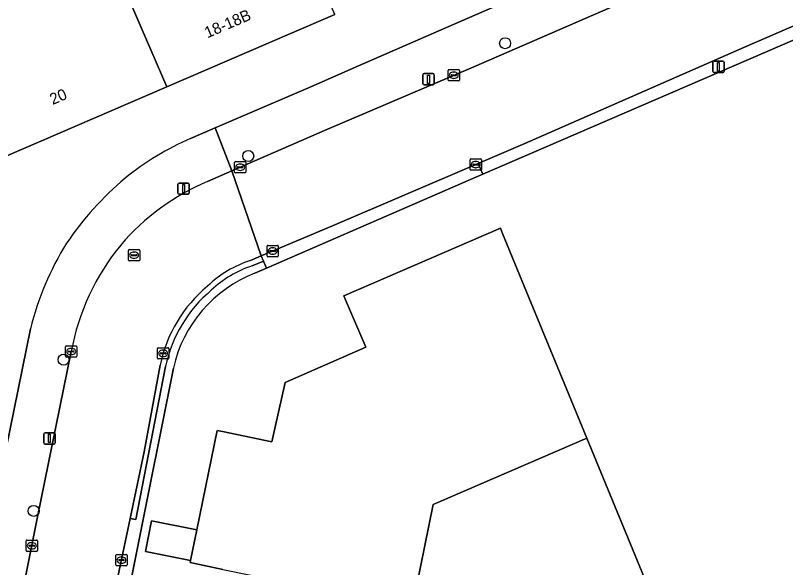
# Model space of a CAD drawing. Extents: x 158086 to 159499, y 382904 to 383981.
# Drawn here: x 158796.6 to 158864.8, y 383041 to 383089.9 of the extents above; entities that cross this region are included whole.
import ezdxf

# ---------------------------------------------------------------- set-up
doc = ezdxf.new("R2010")
doc.units = 0
for name, color, linetype in [('IMGEO_Boom', 7, 'Continuous'), ('IMGEO_Erf', 7, 'Continuous'), ('IMGEO_Kolk', 7, 'Continuous'), ('IMGEO_Lichtmast', 7, 'Continuous'), ('IMGEO_Pand', 7, 'Continuous'), ('IMGEO_Pand_nummerreeks', 7, 'Continuous'), ('IMGEO_Parkeervlak_open', 7, 'Continuous'), ('IMGEO_Rijbaan_lokaal_open', 7, 'Continuous'), ('IMGEO_Rioolput', 7, 'Continuous'), ('IMGEO_Voetpad_open', 7, 'Continuous')]:
    doc.layers.add(name, color=color, linetype=linetype)

msp = doc.modelspace()

# ---------------------------------------------------------------- linework, layer by layer
at = {"layer": 'IMGEO_Boom'}
for centre in [(158839.951, 383087.397), (158817.188, 383077.403), (158800.831, 383059.368), (158798.187, 383045.98)]:
    msp.add_circle(centre, 0.489, dxfattribs=at)
at = {"layer": 'IMGEO_Erf'}
for points in [[(158975.23, 383135.031), (158942.876, 383121.069), (158936.852, 383118.469), (158837.977, 383075.801), (158837.572, 383075.626), (158818.806, 383067.474), (158817.768, 383067.023)], [(158814.931, 383040.798), (158812.043, 383041.411), (158812.078, 383041.581), (158808.08, 383042.398), (158808.633, 383045.106), (158812.631, 383044.289), (158814.431, 383053.094), (158814.905, 383052.997), (158819.271, 383052.105), (158820.475, 383057.358), (158827.618, 383060.492), (158825.82, 383064.663), (158825.666, 383065.019), (158839.541, 383071.003), (158839.731, 383070.541), (158841.445, 383066.38), (158847.197, 383052.411), (158853.12, 383038.028)], [(158810.559, 383058.63), (158807.3, 383042.268), (158806.424, 383037.984), (158805.395, 383032.947), (158801.03, 383011.785), (158799.863, 383006.073)]]:
    msp.add_lwpolyline(points, dxfattribs=at)
msp.add_arc((158822.065, 383056.04), 11.794, 111.36692, 167.31253, dxfattribs=at)
at = {"layer": 'IMGEO_Kolk'}
for p, q in [((158834.899, 383084.135), (158834.899, 383084.987)), ((158834.974, 383085.061), (158835.826, 383085.061)), ((158835.9, 383084.987), (158835.9, 383084.135)), ((158835.158, 383084.555), (158835.158, 383084.567)), ((158835.596, 383084.518), (158835.198, 383084.518)), ((158835.201, 383084.604), (158835.599, 383084.604)), ((158835.41, 383084.281), (158835.385, 383084.281)), ((158835.387, 383084.841), (158835.412, 383084.841)), ((158835.642, 383084.567), (158835.642, 383084.555)), ((158835.826, 383084.061), (158834.974, 383084.061)), ((158815.98, 383075.991), (158815.98, 383076.843)), ((158816.055, 383076.917), (158816.907, 383076.917)), ((158816.981, 383076.843), (158816.981, 383075.991)), ((158836.844, 383076.224), (158836.844, 383077.076)), ((158836.919, 383077.15), (158837.771, 383077.15)), ((158837.332, 383076.93), (158837.357, 383076.93)), ((158837.845, 383077.076), (158837.845, 383076.224)), ((158816.239, 383076.411), (158816.239, 383076.423)), ((158816.677, 383076.374), (158816.279, 383076.374)), ((158816.282, 383076.46), (158816.68, 383076.46)), ((158816.491, 383076.137), (158816.466, 383076.137)), ((158816.468, 383076.697), (158816.493, 383076.697)), ((158816.723, 383076.423), (158816.723, 383076.411)), ((158837.771, 383076.15), (158836.919, 383076.15)), ((158837.103, 383076.644), (158837.103, 383076.656)), ((158837.541, 383076.607), (158837.143, 383076.607)), ((158837.146, 383076.693), (158837.544, 383076.693)), ((158837.355, 383076.37), (158837.33, 383076.37)), ((158837.587, 383076.656), (158837.587, 383076.644)), ((158816.907, 383075.917), (158816.055, 383075.917)), ((158818.856, 383068.566), (158818.856, 383069.418)), ((158818.931, 383069.492), (158819.783, 383069.492)), ((158819.344, 383069.272), (158819.369, 383069.272)), ((158819.857, 383069.418), (158819.857, 383068.566)), ((158819.115, 383068.986), (158819.115, 383068.998)), ((158819.553, 383068.949), (158819.155, 383068.949)), ((158819.158, 383069.035), (158819.556, 383069.035)), ((158819.367, 383068.712), (158819.342, 383068.712)), ((158819.599, 383068.998), (158819.599, 383068.986)), ((158819.783, 383068.492), (158818.931, 383068.492)), ((158801.009, 383059.67), (158801.009, 383060.522)), ((158801.084, 383060.596), (158801.936, 383060.596)), ((158801.497, 383060.376), (158801.522, 383060.376)), ((158802.01, 383060.522), (158802.01, 383059.67)), ((158809.226, 383060.433), (158810.078, 383060.433)), ((158801.268, 383060.09), (158801.268, 383060.102)), ((158801.706, 383060.053), (158801.308, 383060.053)), ((158801.311, 383060.139), (158801.709, 383060.139)), ((158801.52, 383059.816), (158801.495, 383059.816)), ((158801.752, 383060.102), (158801.752, 383060.09)), ((158809.151, 383059.507), (158809.151, 383060.359)), ((158809.41, 383059.927), (158809.41, 383059.939)), ((158809.848, 383059.89), (158809.45, 383059.89)), ((158809.453, 383059.976), (158809.851, 383059.976)), ((158809.639, 383060.213), (158809.664, 383060.213)), ((158809.894, 383059.939), (158809.894, 383059.927)), ((158810.152, 383060.359), (158810.152, 383059.507)), ((158801.936, 383059.596), (158801.084, 383059.596)), ((158810.078, 383059.433), (158809.226, 383059.433)), ((158809.662, 383059.653), (158809.637, 383059.653)), ((158797.52, 383042.47), (158797.52, 383043.322)), ((158797.595, 383043.396), (158798.447, 383043.396)), ((158798.521, 383043.322), (158798.521, 383042.47)), ((158797.779, 383042.89), (158797.779, 383042.902)), ((158798.217, 383042.853), (158797.819, 383042.853)), ((158797.822, 383042.939), (158798.22, 383042.939)), ((158798.008, 383043.176), (158798.033, 383043.176)), ((158798.263, 383042.902), (158798.263, 383042.89)), ((158798.447, 383042.396), (158797.595, 383042.396)), ((158798.031, 383042.616), (158798.006, 383042.616)), ((158805.455, 383041.196), (158805.455, 383042.048)), ((158805.53, 383042.122), (158806.382, 383042.122)), ((158806.456, 383042.048), (158806.456, 383041.196)), ((158805.714, 383041.616), (158805.714, 383041.628)), ((158806.152, 383041.579), (158805.754, 383041.579)), ((158805.757, 383041.665), (158806.155, 383041.665)), ((158805.966, 383041.342), (158805.941, 383041.342)), ((158805.943, 383041.902), (158805.968, 383041.902)), ((158806.198, 383041.628), (158806.198, 383041.616)), ((158806.382, 383041.122), (158805.53, 383041.122))]:
    msp.add_line(p, q, dxfattribs=at)
for points in [[(158834.899, 383084.135), (158834.899, 383084.987)], [(158834.974, 383085.061), (158835.826, 383085.061)], [(158835.9, 383084.987), (158835.9, 383084.135)], [(158835.826, 383084.061), (158834.974, 383084.061)], [(158815.98, 383075.991), (158815.98, 383076.843)], [(158816.055, 383076.917), (158816.907, 383076.917)], [(158816.981, 383076.843), (158816.981, 383075.991)], [(158836.844, 383076.224), (158836.844, 383077.076)], [(158836.919, 383077.15), (158837.771, 383077.15)], [(158837.845, 383077.076), (158837.845, 383076.224)], [(158837.771, 383076.15), (158836.919, 383076.15)], [(158816.907, 383075.917), (158816.055, 383075.917)], [(158818.856, 383068.566), (158818.856, 383069.418)], [(158818.931, 383069.492), (158819.783, 383069.492)], [(158819.857, 383069.418), (158819.857, 383068.566)], [(158819.783, 383068.492), (158818.931, 383068.492)], [(158801.009, 383059.67), (158801.009, 383060.522)], [(158801.084, 383060.596), (158801.936, 383060.596)], [(158802.01, 383060.522), (158802.01, 383059.67)], [(158809.226, 383060.433), (158810.078, 383060.433)], [(158809.151, 383059.507), (158809.151, 383060.359)], [(158810.152, 383060.359), (158810.152, 383059.507)], [(158801.936, 383059.596), (158801.084, 383059.596)], [(158810.078, 383059.433), (158809.226, 383059.433)], [(158797.52, 383042.47), (158797.52, 383043.322)], [(158797.595, 383043.396), (158798.447, 383043.396)], [(158798.521, 383043.322), (158798.521, 383042.47)], [(158798.447, 383042.396), (158797.595, 383042.396)], [(158805.455, 383041.196), (158805.455, 383042.048)], [(158805.53, 383042.122), (158806.382, 383042.122)], [(158806.456, 383042.048), (158806.456, 383041.196)], [(158806.382, 383041.122), (158805.53, 383041.122)]]:
    msp.add_lwpolyline(points, dxfattribs=at)
for centre, radius, start, end in [((158834.976, 383084.985), 0.0765, 91.55205, 178.44795), ((158834.976, 383084.985), 0.0765, 91.55205, 178.44795), ((158835.824, 383084.985), 0.0765, 1.55205, 88.44795), ((158835.824, 383084.985), 0.0765, 1.55205, 88.44795), ((158835.198, 383084.564), 0.0403, 85.87752, 175.75265), ((158835.195, 383084.554), 0.0366, 178.93798, 274.71019), ((158835.599, 383084.561), 0.043, 264.86636, 352.45326), ((158835.603, 383084.566), 0.0386, 1.73085, 96.63898), ((158834.976, 383084.137), 0.0765, 181.55205, 268.44795), ((158834.976, 383084.137), 0.0765, 181.55205, 268.44795), ((158835.824, 383084.137), 0.0765, 271.55205, 358.44795), ((158835.824, 383084.137), 0.0765, 271.55205, 358.44795), ((158816.057, 383076.841), 0.0765, 91.55205, 178.44795), ((158816.057, 383076.841), 0.0765, 91.55205, 178.44795), ((158816.905, 383076.841), 0.0765, 1.55205, 88.44795), ((158816.905, 383076.841), 0.0765, 1.55205, 88.44795), ((158836.921, 383077.074), 0.0765, 91.55205, 178.44795), ((158836.921, 383077.074), 0.0765, 91.55205, 178.44795), ((158837.769, 383077.074), 0.0765, 1.55205, 88.44795), ((158837.769, 383077.074), 0.0765, 1.55205, 88.44795), ((158816.279, 383076.42), 0.0403, 85.87752, 175.75265), ((158816.276, 383076.41), 0.0366, 178.93798, 274.71019), ((158816.68, 383076.417), 0.043, 264.86636, 352.45326), ((158816.684, 383076.422), 0.0386, 1.73085, 96.63898), ((158836.921, 383076.226), 0.0765, 181.55205, 268.44795), ((158836.921, 383076.226), 0.0765, 181.55205, 268.44795), ((158837.143, 383076.653), 0.0403, 85.87752, 175.75265), ((158837.14, 383076.643), 0.0366, 178.93798, 274.71019), ((158837.544, 383076.65), 0.043, 264.86636, 352.45326), ((158837.548, 383076.655), 0.0386, 1.73085, 96.63898), ((158837.769, 383076.226), 0.0765, 271.55205, 358.44795), ((158837.769, 383076.226), 0.0765, 271.55205, 358.44795), ((158816.057, 383075.993), 0.0765, 181.55205, 268.44795), ((158816.057, 383075.993), 0.0765, 181.55205, 268.44795), ((158816.905, 383075.993), 0.0765, 271.55205, 358.44795), ((158816.905, 383075.993), 0.0765, 271.55205, 358.44795), ((158818.933, 383069.416), 0.0765, 91.55205, 178.44795), ((158818.933, 383069.416), 0.0765, 91.55205, 178.44795), ((158819.781, 383069.416), 0.0765, 1.55205, 88.44795), ((158819.781, 383069.416), 0.0765, 1.55205, 88.44795), ((158818.933, 383068.568), 0.0765, 181.55205, 268.44795), ((158818.933, 383068.568), 0.0765, 181.55205, 268.44795), ((158819.155, 383068.995), 0.0403, 85.87752, 175.75265), ((158819.152, 383068.985), 0.0366, 178.93798, 274.71019), ((158819.556, 383068.992), 0.043, 264.86636, 352.45326), ((158819.56, 383068.997), 0.0386, 1.73085, 96.63898), ((158819.781, 383068.568), 0.0765, 271.55205, 358.44795), ((158819.781, 383068.568), 0.0765, 271.55205, 358.44795), ((158801.086, 383060.52), 0.0765, 91.55205, 178.44795), ((158801.086, 383060.52), 0.0765, 91.55205, 178.44795), ((158801.934, 383060.52), 0.0765, 1.55205, 88.44795), ((158801.934, 383060.52), 0.0765, 1.55205, 88.44795), ((158809.228, 383060.357), 0.0765, 91.55205, 178.44795), ((158809.228, 383060.357), 0.0765, 91.55205, 178.44795), ((158810.076, 383060.357), 0.0765, 1.55205, 88.44795), ((158810.076, 383060.357), 0.0765, 1.55205, 88.44795), ((158801.308, 383060.099), 0.0403, 85.87752, 175.75265), ((158801.305, 383060.089), 0.0366, 178.93798, 274.71019), ((158801.709, 383060.096), 0.043, 264.86636, 352.45326), ((158801.713, 383060.101), 0.0386, 1.73085, 96.63898), ((158809.45, 383059.936), 0.0403, 85.87752, 175.75265), ((158809.447, 383059.926), 0.0366, 178.93798, 274.71019), ((158809.851, 383059.933), 0.043, 264.86636, 352.45326), ((158809.855, 383059.938), 0.0386, 1.73085, 96.63898), ((158801.086, 383059.672), 0.0765, 181.55205, 268.44795), ((158801.086, 383059.672), 0.0765, 181.55205, 268.44795), ((158801.934, 383059.672), 0.0765, 271.55205, 358.44795), ((158801.934, 383059.672), 0.0765, 271.55205, 358.44795), ((158809.228, 383059.509), 0.0765, 181.55205, 268.44795), ((158809.228, 383059.509), 0.0765, 181.55205, 268.44795), ((158810.076, 383059.509), 0.0765, 271.55205, 358.44795), ((158810.076, 383059.509), 0.0765, 271.55205, 358.44795), ((158797.597, 383043.32), 0.0765, 91.55205, 178.44795), ((158797.597, 383043.32), 0.0765, 91.55205, 178.44795), ((158798.445, 383043.32), 0.0765, 1.55205, 88.44795), ((158798.445, 383043.32), 0.0765, 1.55205, 88.44795), ((158797.819, 383042.899), 0.0403, 85.87752, 175.75265), ((158797.816, 383042.889), 0.0366, 178.93798, 274.71019), ((158798.22, 383042.896), 0.043, 264.86636, 352.45326), ((158798.224, 383042.901), 0.0386, 1.73085, 96.63898), ((158797.597, 383042.472), 0.0765, 181.55205, 268.44795), ((158797.597, 383042.472), 0.0765, 181.55205, 268.44795), ((158798.445, 383042.472), 0.0765, 271.55205, 358.44795), ((158798.445, 383042.472), 0.0765, 271.55205, 358.44795), ((158805.532, 383042.046), 0.0765, 91.55205, 178.44795), ((158805.532, 383042.046), 0.0765, 91.55205, 178.44795), ((158806.38, 383042.046), 0.0765, 1.55205, 88.44795), ((158806.38, 383042.046), 0.0765, 1.55205, 88.44795), ((158805.754, 383041.625), 0.0403, 85.87752, 175.75265), ((158805.751, 383041.615), 0.0366, 178.93798, 274.71019), ((158806.155, 383041.622), 0.043, 264.86636, 352.45326), ((158806.159, 383041.627), 0.0386, 1.73085, 96.63898), ((158805.532, 383041.198), 0.0765, 181.55205, 268.44795), ((158805.532, 383041.198), 0.0765, 181.55205, 268.44795), ((158806.38, 383041.198), 0.0765, 271.55205, 358.44795), ((158806.38, 383041.198), 0.0765, 271.55205, 358.44795)]:
    msp.add_arc(centre, radius, start, end, dxfattribs=at)
for centre, major_axis, ratio, start_param, end_param in [((158835.386, 383084.561), (-0.387, 0.002), 0.722429, 4.712389, 7.853982), ((158835.411, 383084.561), (-0.39, 0.002), 0.717154, 1.570796, 4.712389), ((158837.331, 383076.65), (-0.387, 0.002), 0.722429, 4.712389, 7.853982), ((158837.356, 383076.65), (-0.39, 0.002), 0.717154, 1.570796, 4.712389), ((158816.467, 383076.417), (-0.387, 0.002), 0.722429, 4.712389, 7.853982), ((158816.492, 383076.417), (-0.39, 0.002), 0.717154, 1.570796, 4.712389), ((158819.343, 383068.992), (-0.387, 0.002), 0.722429, 4.712389, 7.853982), ((158819.368, 383068.992), (-0.39, 0.002), 0.717154, 1.570796, 4.712389), ((158801.496, 383060.096), (-0.387, 0.002), 0.722429, 4.712389, 7.853982), ((158801.521, 383060.096), (-0.39, 0.002), 0.717154, 1.570796, 4.712389), ((158809.638, 383059.933), (-0.387, 0.002), 0.722429, 4.712389, 7.853982), ((158809.663, 383059.933), (-0.39, 0.002), 0.717154, 1.570796, 4.712389), ((158798.007, 383042.896), (-0.387, 0.002), 0.722429, 4.712389, 7.853982), ((158798.032, 383042.896), (-0.39, 0.002), 0.717154, 1.570796, 4.712389), ((158805.942, 383041.622), (-0.387, 0.002), 0.722429, 4.712389, 7.853982), ((158805.967, 383041.622), (-0.39, 0.002), 0.717154, 1.570796, 4.712389)]:
    msp.add_ellipse(centre, major_axis=major_axis, ratio=ratio, start_param=start_param, end_param=end_param, dxfattribs=at)
at = {"layer": 'IMGEO_Lichtmast'}
for p, q in [((158858.357, 383084.904), (158858.357, 383085.704)), ((158858.357, 383085.704), (158858.357, 383084.904)), ((158858.457, 383085.804), (158859.247, 383085.804)), ((158859.247, 383085.804), (158858.457, 383085.804)), ((158859.347, 383085.704), (158859.347, 383084.904)), ((158859.347, 383084.904), (158859.347, 383085.704)), ((158832.668, 383083.799), (158832.668, 383084.599)), ((158832.668, 383084.599), (158832.668, 383083.799)), ((158832.768, 383084.699), (158833.558, 383084.699)), ((158833.558, 383084.699), (158832.768, 383084.699)), ((158833.658, 383084.599), (158833.658, 383083.799)), ((158833.658, 383083.799), (158833.658, 383084.599)), ((158859.247, 383084.804), (158858.457, 383084.804)), ((158858.457, 383084.804), (158859.247, 383084.804)), ((158833.558, 383083.699), (158832.768, 383083.699)), ((158832.768, 383083.699), (158833.558, 383083.699)), ((158810.966, 383074.114), (158810.966, 383074.914)), ((158810.966, 383074.914), (158810.966, 383074.114)), ((158811.066, 383075.014), (158811.856, 383075.014)), ((158811.856, 383075.014), (158811.066, 383075.014)), ((158811.956, 383074.914), (158811.956, 383074.114)), ((158811.956, 383074.114), (158811.956, 383074.914)), ((158811.856, 383074.014), (158811.066, 383074.014)), ((158811.066, 383074.014), (158811.856, 383074.014)), ((158799.188, 383052.901), (158799.978, 383052.901)), ((158799.978, 383052.901), (158799.188, 383052.901)), ((158799.088, 383052.001), (158799.088, 383052.801)), ((158799.088, 383052.801), (158799.088, 383052.001)), ((158800.078, 383052.801), (158800.078, 383052.001)), ((158800.078, 383052.001), (158800.078, 383052.801)), ((158799.978, 383051.901), (158799.188, 383051.901)), ((158799.188, 383051.901), (158799.978, 383051.901))]:
    msp.add_line(p, q, dxfattribs=at)
for points in [[(158858.777, 383085.679), (158858.927, 383085.679), (158858.927, 383084.929), (158858.777, 383084.929), (158858.777, 383085.679)], [(158833.088, 383084.574), (158833.238, 383084.574), (158833.238, 383083.824), (158833.088, 383083.824), (158833.088, 383084.574)], [(158811.386, 383074.889), (158811.536, 383074.889), (158811.536, 383074.139), (158811.386, 383074.139), (158811.386, 383074.889)], [(158799.508, 383052.776), (158799.658, 383052.776), (158799.658, 383052.026), (158799.508, 383052.026), (158799.508, 383052.776)]]:
    msp.add_lwpolyline(points, dxfattribs=at)
for centre, start, end in [((158858.457, 383085.704), 90, 180), ((158858.457, 383085.704), 90, 180), ((158859.247, 383085.704), 0, 90), ((158859.247, 383085.704), 360, 90), ((158832.768, 383084.599), 90, 180), ((158832.768, 383084.599), 90, 180), ((158833.558, 383084.599), 0, 90), ((158833.558, 383084.599), 360, 90), ((158858.457, 383084.904), 180, 270), ((158858.457, 383084.904), 180, 270), ((158859.247, 383084.904), 270, 0), ((158859.247, 383084.904), 270, 0), ((158832.768, 383083.799), 180, 270), ((158832.768, 383083.799), 180, 270), ((158833.558, 383083.799), 270, 0), ((158833.558, 383083.799), 270, 0), ((158811.066, 383074.914), 90, 180), ((158811.066, 383074.914), 90, 180), ((158811.856, 383074.914), 0, 90), ((158811.856, 383074.914), 360, 90), ((158811.066, 383074.114), 180, 270), ((158811.066, 383074.114), 180, 270), ((158811.856, 383074.114), 270, 0), ((158811.856, 383074.114), 270, 0), ((158799.188, 383052.801), 90, 180), ((158799.188, 383052.801), 90, 180), ((158799.978, 383052.801), 0, 90), ((158799.978, 383052.801), 360, 90), ((158799.188, 383052.001), 180, 270), ((158799.188, 383052.001), 180, 270), ((158799.978, 383052.001), 270, 0), ((158799.978, 383052.001), 270, 0)]:
    msp.add_arc(centre, 0.1, start, end, dxfattribs=at)
at = {"layer": 'IMGEO_Pand'}
for points in [[(158815.168, 383112.219), (158814.516, 383113.718), (158799.697, 383107.335), (158800.419, 383105.658), (158809.97, 383083.526), (158820.883, 383088.227), (158824.863, 383089.942)], [(158783.762, 383098.483), (158793.286, 383076.339), (158795.608, 383077.34), (158809.97, 383083.526), (158800.419, 383105.658)], [(158841.445, 383066.38), (158839.731, 383070.541), (158839.541, 383071.003), (158825.666, 383065.019), (158825.82, 383064.663), (158827.618, 383060.492), (158820.475, 383057.358), (158819.271, 383052.105), (158814.905, 383052.997), (158814.431, 383053.094), (158812.631, 383044.289), (158812.078, 383041.581), (158812.043, 383041.411), (158814.931, 383040.798), (158831.715, 383037.39), (158833.572, 383046.532), (158847.197, 383052.411)], [(158827.937, 383018.939), (158836.719, 383017.145), (158834.361, 383006.129), (158833.357, 383001.231), (158839.363, 383000), (158845.135, 382998.817), (158845.331, 382999.777), (158845.507, 382999.741), (158845.561, 383000), (158851.85, 383030.234), (158851.536, 383030.298), (158853.12, 383038.028), (158847.197, 383052.411), (158833.572, 383046.532), (158831.715, 383037.39)], [(158812.631, 383044.289), (158808.633, 383045.106), (158808.08, 383042.398), (158812.078, 383041.581)]]:
    msp.add_lwpolyline(points, close=True, dxfattribs=at)
at = {"layer": 'IMGEO_Parkeervlak_open'}
for points in [[(158812.082, 383078.952), (158814.262, 383079.888), (158822.73, 383083.523), (158826.959, 383085.407), (158837.267, 383089.875), (158855.36, 383097.718)], [(158824.863, 383089.942), (158820.883, 383088.227), (158809.97, 383083.526), (158795.608, 383077.34), (158793.9, 383068.563), (158791.767, 383057.954), (158789.816, 383048.453), (158788.884, 383048.644), (158788.619, 383047.357), (158794.614, 383046.144), (158797.897, 383062.091)]]:
    msp.add_lwpolyline(points, dxfattribs=at)
for centre, radius, start, end in [((158821.81, 383056.377), 24.582, 113.31105, 129.1643), ((158824.024, 383054.249), 27.633, 129.9378, 146.057), ((158822.818, 383056.04), 25.645, 147.8724, 166.35162)]:
    msp.add_arc(centre, radius, start, end, dxfattribs=at)
at = {"layer": 'IMGEO_Rijbaan_lokaal_open'}
for points in [[(158860.515, 383095.469), (158837.171, 383085.317), (158823.954, 383079.663), (158815.746, 383076.096), (158818.333, 383068.56), (158824.654, 383071.232), (158837.57, 383076.747), (158841.699, 383078.51), (158861.173, 383087.039), (158876.569, 383093.744)], [(158817.395, 383068.163), (158818.333, 383068.56), (158815.746, 383076.096), (158813.597, 383075.162)], [(158801.51, 383060.092), (158798.504, 383045.305), (158796.167, 383033.685), (158793.719, 383021.9), (158793.205, 383018.967), (158792.953, 383017.671), (158792.923, 383017.513), (158792.054, 383011.53), (158791.145, 383007.213)], [(158798.725, 383004.808), (158800.707, 383015.34), (158801.166, 383018.431), (158802.528, 383025.095), (158802.686, 383025.857), (158804.207, 383033.195), (158805.259, 383038.227), (158805.761, 383040.697), (158806.731, 383045.313), (158807.971, 383051.215), (158809.383, 383058.871)]]:
    msp.add_lwpolyline(points, dxfattribs=at)
for centre, radius, start, end in [((158821.836, 383055.818), 21.026, 113.07071, 139.32019), ((158822.036, 383056.29), 20.875, 140.66093, 169.50633), ((158820.528, 383058.597), 10.066, 108.13112, 133.66831), ((158821.481, 383056.388), 12.35, 129.7919, 168.40332)]:
    msp.add_arc(centre, radius, start, end, dxfattribs=at)
at = {"layer": 'IMGEO_Rioolput'}
for p, q in [((158806.575, 383068.198), (158806.575, 383069.05)), ((158806.65, 383069.124), (158807.502, 383069.124)), ((158806.834, 383068.618), (158806.834, 383068.63)), ((158807.272, 383068.581), (158806.874, 383068.581)), ((158806.877, 383068.667), (158807.275, 383068.667)), ((158807.063, 383068.904), (158807.088, 383068.904)), ((158807.318, 383068.63), (158807.318, 383068.618)), ((158807.576, 383069.05), (158807.576, 383068.198)), ((158807.502, 383068.124), (158806.65, 383068.124)), ((158807.086, 383068.344), (158807.061, 383068.344))]:
    msp.add_line(p, q, dxfattribs=at)
for points in [[(158806.575, 383068.198), (158806.575, 383069.05)], [(158806.65, 383069.124), (158807.502, 383069.124)], [(158807.576, 383069.05), (158807.576, 383068.198)], [(158807.502, 383068.124), (158806.65, 383068.124)]]:
    msp.add_lwpolyline(points, dxfattribs=at)
for centre, radius, start, end in [((158806.652, 383069.048), 0.0765, 91.55205, 178.44795), ((158806.652, 383069.048), 0.0765, 91.55205, 178.44795), ((158806.874, 383068.627), 0.0403, 85.87752, 175.75265), ((158806.871, 383068.617), 0.0366, 178.93798, 274.71019), ((158807.275, 383068.624), 0.043, 264.86636, 352.45326), ((158807.279, 383068.629), 0.0386, 1.73085, 96.63898), ((158807.5, 383069.048), 0.0765, 1.55205, 88.44795), ((158807.5, 383069.048), 0.0765, 1.55205, 88.44795), ((158806.652, 383068.2), 0.0765, 181.55205, 268.44795), ((158806.652, 383068.2), 0.0765, 181.55205, 268.44795), ((158807.5, 383068.2), 0.0765, 271.55205, 358.44795), ((158807.5, 383068.2), 0.0765, 271.55205, 358.44795)]:
    msp.add_arc(centre, radius, start, end, dxfattribs=at)
for centre, major_axis, ratio, start_param, end_param in [((158807.062, 383068.624), (-0.387, 0.002), 0.722429, 4.712389, 7.853982), ((158807.087, 383068.624), (-0.39, 0.002), 0.717154, 1.570796, 4.712389)]:
    msp.add_ellipse(centre, major_axis=major_axis, ratio=ratio, start_param=start_param, end_param=end_param, dxfattribs=at)
at = {"layer": 'IMGEO_Voetpad_open'}
for points in [[(158860.515, 383095.469), (158869.573, 383099.365), (158884.677, 383105.886), (158890.378, 383108.368), (158901.627, 383113.355), (158906.765, 383115.503), (158904.772, 383119.136), (158855.36, 383097.718), (158837.267, 383089.875), (158826.959, 383085.407), (158822.73, 383083.523), (158814.262, 383079.888), (158815.746, 383076.096), (158823.954, 383079.663), (158837.171, 383085.317)], [(158936.388, 383119.543), (158919.966, 383112.427), (158889.932, 383099.442), (158876.569, 383093.744), (158861.173, 383087.039), (158841.699, 383078.51), (158837.57, 383076.747), (158837.977, 383075.801), (158936.852, 383118.469), (158936.586, 383119.085)], [(158837.572, 383075.626), (158837.977, 383075.801), (158837.57, 383076.747), (158824.654, 383071.232), (158818.333, 383068.56), (158818.533, 383068.101), (158818.806, 383067.474)]]:
    msp.add_lwpolyline(points, close=True, dxfattribs=at)
for points in [[(158814.262, 383079.888), (158812.082, 383078.952)], [(158813.597, 383075.162), (158815.746, 383076.096), (158814.262, 383079.888)], [(158817.551, 383067.688), (158818.533, 383068.101), (158818.333, 383068.56), (158817.395, 383068.163)], [(158817.768, 383067.023), (158818.806, 383067.474), (158818.533, 383068.101), (158817.551, 383067.688)], [(158797.897, 383062.091), (158794.614, 383046.144), (158789.4, 383020.358), (158792.953, 383017.671), (158793.205, 383018.967), (158793.719, 383021.9), (158796.167, 383033.685), (158798.504, 383045.305), (158801.51, 383060.092)], [(158809.875, 383058.777), (158807.219, 383045.208), (158806.731, 383045.313), (158805.761, 383040.697), (158805.259, 383038.227), (158806.424, 383037.984), (158807.3, 383042.268), (158810.559, 383058.63)], [(158809.383, 383058.871), (158807.971, 383051.215), (158806.731, 383045.313), (158807.219, 383045.208), (158809.875, 383058.777)]]:
    msp.add_lwpolyline(points, dxfattribs=at)
for centre, radius, start, end in [((158821.81, 383056.377), 24.582, 113.31105, 129.1643), ((158824.024, 383054.249), 27.633, 129.9378, 146.057), ((158821.836, 383055.818), 21.026, 113.07071, 139.32019), ((158822.818, 383056.04), 25.645, 147.8724, 166.35162), ((158822.036, 383056.29), 20.875, 140.66093, 169.50633), ((158820.528, 383058.597), 10.066, 108.13112, 133.66831), ((158820.529, 383058.594), 9.569, 108.13395, 133.6681), ((158820.529, 383058.594), 9.569, 108.13395, 133.6681), ((158822.065, 383056.04), 11.794, 111.36692, 167.31253), ((158821.481, 383056.388), 12.35, 129.7919, 168.40332), ((158821.53, 383056.362), 11.903, 129.73253, 168.29496), ((158821.53, 383056.362), 11.903, 129.73253, 168.29496)]:
    msp.add_arc(centre, radius, start, end, dxfattribs=at)

# ---------------------------------------------------------------- texts
at = {"layer": 'IMGEO_Pand_nummerreeks'}
for s, rotation, p in [('18-18B', 23.30792, (158813.576, 383087.824)), ('20', 23.30636, (158799.867, 383081.918))]:
    msp.add_text(s, height=1, rotation=rotation, dxfattribs=at).set_placement(p)

doc.saveas('drawing.dxf')
